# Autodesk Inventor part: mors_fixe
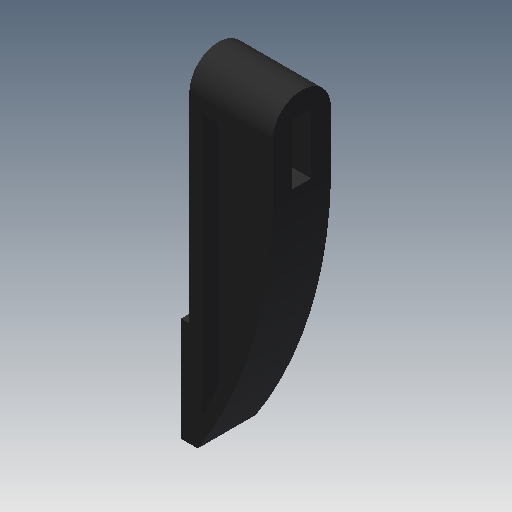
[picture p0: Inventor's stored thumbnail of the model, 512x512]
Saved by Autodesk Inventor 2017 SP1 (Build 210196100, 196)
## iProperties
Shininess: 64.0
Length Units: 11269
Angle Units: 11279
Time Units: 11290
Mass Units: 11283
Length Display Precision: 3
Angle Display Precision: 2
Compacted: True
Part Number: mors_fixe
Document SubType Name: Modeling
Created: 2003-07
Material: Générique
Designer: trameau
Density: 1 g/cm^3
Appearance: Caoutchouc (Noir)
Density: 0.0
Volumn: 0.0
Area: 0.0
PropertySet Name: Model Information
Control State: 0
Master: False
Checked Out: False
Author: trameau
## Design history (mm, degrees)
sketch "Esquisse1"
  geometry: L1 (-7.126, -9.553)-(-7.126, 15.447); L2 (-7.126, 15.447)-(-5.126, 15.447); L3 (-5.126, 15.447)-(-5.126, 70.447); L4 (-5.126, 70.447)-(14.874, 70.447); L5 (14.874, 70.447)-(14.874, 48.447); L6 (-7.126, -9.553)-(-3.126, -9.553); A1 r 113.124 centre (-98.202, 51.746) between (-3.126, -9.553) and (14.874, 48.447)
  constraints: 12 end point, 3 parallel, 2 perpendicular, 2 point on circle, 1 centre point, 1 vertical
  dimensions: "d0" = 80 distance between parallel lines of L6 L4; "d1" = 22 distance of L4.end L5.end; "d2" = 20 distance of L3.end L4.end; "d3" = 2 distance between parallel lines of L3 L1; "d4" = 25 distance of L1.start L1.end; "d5" = 4 distance of L1.start L6.end
extrude "Extrusion1" new body sketch "Esquisse1" distance "d6" = 14; taper "d7" = 0 deg
fillet "Congé1" dims "d8" = 7
sketch "Esquisse2"
  geometry: L1 (-5.126, 63.447)-(14.874, 63.447) reference; L2 (-5.126, 15.447)-(-5.126, 63.447) reference; L3 (14.874, 63.447)-(14.874, 48.447) reference; L4 (11.874, 48.491)-(11.874, 60.447); L5 (11.874, 60.447)-(-2.126, 60.447); L6 (-2.126, 60.447)-(-2.126, -2.075); A1 r 113.124 centre (-98.202, 51.746) between (-3.126, -9.553) and (14.874, 48.447) reference; A2 r 110.124 centre (-98.202, 51.746) between (-2.126, -2.075) and (11.874, 48.491)
  constraints: 6 end point, 2 point on circle, 1 centre point, 1 other
  dimensions: "d9" = 3 distance between parallel lines of L2 L6
extrude "Extrusion2" cut sketch "Esquisse2" distance "d10" = 4; taper "d11" = 0 deg
node "Axe de construction1"
node "Plan de construction1"
mirror "Symétrie1"
sketch "Esquisse3"
  geometry: L1 (4.75, 50)-(9.25, 50); L2 (9.25, 50)-(9.25, 35.5); L3 (9.25, 35.5)-(4.75, 35.5); L4 (4.75, 35.5)-(4.75, 50); A1 r 7 centre (7, 48) between (14, 48) and (0, 48) reference
  constraints: 8 end point, 2 parallel, 1 horizontal, 1 perpendicular
  dimensions: "d13" = 2 distance from line of A1.centre L1; "d14" = 4.5 distance of L1.start L1.end; "d15" = 2.25 distance from line of A1.centre L2 (= 0.5 x d14); "d16" = 14.5 distance of L1.end L2.end
extrude "Extrusion3" cut sketch "Esquisse3" stored distance "d17" = 4; taper "d18" = 0 deg
node "Solide1"
node "Corps solides"
node "Corps surfaciques"
other parameters: "d12" = 0
